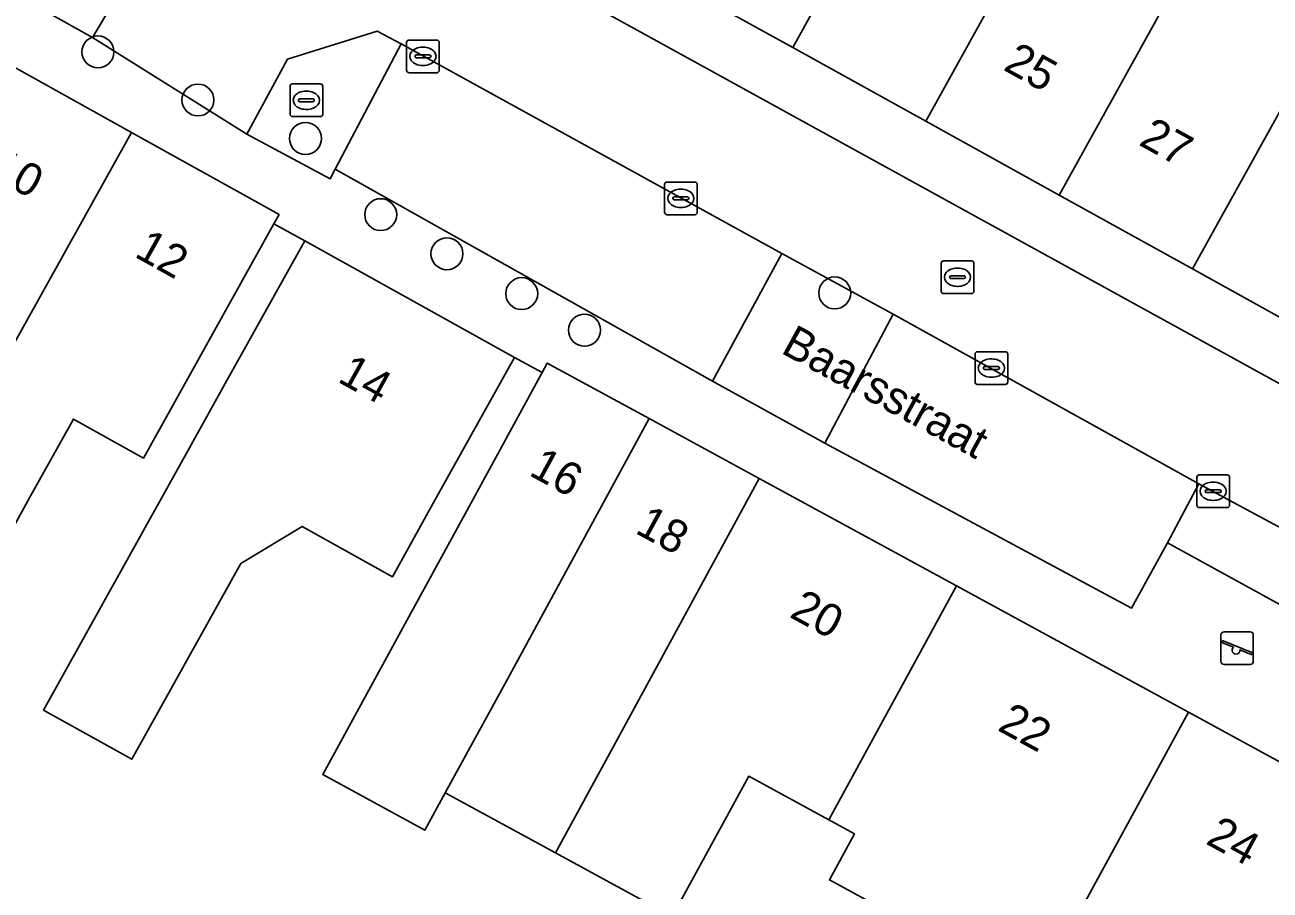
# Model space of a CAD drawing. Extents: x 160102 to 160934, y 382045 to 382923.
# Drawn here: x 160331.35 to 160369.43, y 382187.9 to 382214.38 of the extents above; entities that cross this region are included whole.
import ezdxf

# ---------------------------------------------------------------- set-up
doc = ezdxf.new("R2010")
doc.units = 0
for name, color, linetype in [('IMGEO_Boom', 7, 'Continuous'), ('IMGEO_Brandkraan', 7, 'Continuous'), ('IMGEO_Erf', 7, 'Continuous'), ('IMGEO_Groenvoorziening', 7, 'Continuous'), ('IMGEO_Kolk', 7, 'Continuous'), ('IMGEO_Openbare_ruimte_label', 7, 'Continuous'), ('IMGEO_Pand', 7, 'Continuous'), ('IMGEO_Pand_nummerreeks', 7, 'Continuous'), ('IMGEO_Parkeervlak_open', 7, 'Continuous'), ('IMGEO_Rioolput', 7, 'Continuous'), ('IMGEO_Speelvoorziening', 7, 'Continuous'), ('IMGEO_Verkeerseiland_open', 7, 'Continuous'), ('IMGEO_Voetpad_open', 7, 'Continuous'), ('IMGEO_Woonerf_open', 7, 'Continuous')]:
    doc.layers.add(name, color=color, linetype=linetype)

msp = doc.modelspace()

# ---------------------------------------------------------------- linework, layer by layer
at = {"layer": 'IMGEO_Boom'}
for centre in [(160333.58, 382213.551), (160336.638, 382212.08), (160339.927, 382210.904), (160342.228, 382208.572), (160344.255, 382207.376), (160346.541, 382206.155), (160356.116, 382206.176), (160348.464, 382205.037)]:
    msp.add_circle(centre, 0.489, dxfattribs=at)
at = {"layer": 'IMGEO_Brandkraan'}
for p, q in [((160339.454, 382211.646), (160339.454, 382212.498)), ((160339.529, 382212.572), (160340.381, 382212.572)), ((160339.942, 382212.352), (160339.967, 382212.352)), ((160340.455, 382212.498), (160340.455, 382211.646)), ((160339.713, 382212.066), (160339.713, 382212.078)), ((160340.151, 382212.029), (160339.753, 382212.029)), ((160339.756, 382212.115), (160340.154, 382212.115)), ((160340.197, 382212.078), (160340.197, 382212.066)), ((160340.381, 382211.572), (160339.529, 382211.572)), ((160339.965, 382211.792), (160339.94, 382211.792))]:
    msp.add_line(p, q, dxfattribs=at)
for points in [[(160339.454, 382211.646), (160339.454, 382212.498)], [(160339.529, 382212.572), (160340.381, 382212.572)], [(160340.455, 382212.498), (160340.455, 382211.646)], [(160340.381, 382211.572), (160339.529, 382211.572)]]:
    msp.add_lwpolyline(points, dxfattribs=at)
for centre, radius, start, end in [((160339.531, 382212.496), 0.0765, 91.552, 178.448), ((160339.531, 382212.496), 0.0765, 91.552, 178.448), ((160340.379, 382212.496), 0.0765, 1.552, 88.448), ((160340.379, 382212.496), 0.0765, 1.552, 88.448), ((160339.753, 382212.075), 0.0403, 85.8775, 175.7526), ((160339.75, 382212.065), 0.0366, 178.938, 274.7102), ((160340.154, 382212.072), 0.043, 264.8664, 352.4533), ((160340.158, 382212.077), 0.0386, 1.7309, 96.639), ((160339.531, 382211.648), 0.0765, 181.552, 268.448), ((160339.531, 382211.648), 0.0765, 181.552, 268.448), ((160340.379, 382211.648), 0.0765, 271.552, 358.448), ((160340.379, 382211.648), 0.0765, 271.552, 358.448)]:
    msp.add_arc(centre, radius, start, end, dxfattribs=at)
for centre, major_axis, ratio, start_param, end_param in [((160339.941, 382212.072), (-0.387, 0.002), 0.722429, 4.712389, 7.853982), ((160339.966, 382212.072), (-0.39, 0.002), 0.717154, 1.570796, 4.712389)]:
    msp.add_ellipse(centre, major_axis=major_axis, ratio=ratio, start_param=start_param, end_param=end_param, dxfattribs=at)
at = {"layer": 'IMGEO_Erf'}
msp.add_lwpolyline([(160360.772, 382185.588), (160355.952, 382188.213), (160356.721, 382189.624), (160355.937, 382190.051), (160353.484, 382191.388), (160351.144, 382187.095), (160347.573, 382189.041), (160344.203, 382190.877), (160343.583, 382189.739), (160340.462, 382191.439), (160342.97, 382196.042), (160344.93, 382199.64), (160347.164, 382203.74), (160346.32, 382204.199), (160343.888, 382199.831), (160342.586, 382197.494), (160339.822, 382199.033), (160337.95, 382197.902), (160334.611, 382191.909), (160331.911, 382193.413), (160336.173, 382201.065), (160337.475, 382203.402), (160339.908, 382207.77), (160338.963, 382208.291), (160336.687, 382204.205), (160334.972, 382201.125), (160332.831, 382202.317), (160331.498, 382199.923), (160330.295, 382197.745)], dxfattribs=at)
at = {"layer": 'IMGEO_Groenvoorziening'}
for points in [[(160342.857, 382213.798), (160342.12, 382214.184), (160339.373, 382213.33), (160338.13, 382211.039), (160340.683, 382209.668), (160340.84, 382209.967)], [(160371.499, 382195.671), (160371.728, 382196.05), (160370.985, 382198.327), (160367.256, 382200.334), (160366.293, 382198.53)]]:
    msp.add_lwpolyline(points, close=True, dxfattribs=at)
at = {"layer": 'IMGEO_Kolk'}
for p, q in [((160343.019, 382212.989), (160343.019, 382213.841)), ((160343.094, 382213.915), (160343.946, 382213.915)), ((160344.02, 382213.841), (160344.02, 382212.989)), ((160343.321, 382213.458), (160343.719, 382213.458)), ((160343.507, 382213.695), (160343.532, 382213.695)), ((160343.278, 382213.409), (160343.278, 382213.421)), ((160343.716, 382213.372), (160343.318, 382213.372)), ((160343.53, 382213.135), (160343.505, 382213.135)), ((160343.762, 382213.421), (160343.762, 382213.409)), ((160343.946, 382212.915), (160343.094, 382212.915)), ((160350.909, 382208.645), (160350.909, 382209.497)), ((160350.984, 382209.571), (160351.836, 382209.571)), ((160351.397, 382209.351), (160351.422, 382209.351)), ((160351.91, 382209.497), (160351.91, 382208.645)), ((160351.168, 382209.065), (160351.168, 382209.077)), ((160351.606, 382209.028), (160351.208, 382209.028)), ((160351.211, 382209.114), (160351.609, 382209.114)), ((160351.652, 382209.077), (160351.652, 382209.065)), ((160351.836, 382208.571), (160350.984, 382208.571)), ((160351.42, 382208.791), (160351.395, 382208.791)), ((160360.409, 382203.452), (160360.409, 382204.304)), ((160360.484, 382204.378), (160361.336, 382204.378)), ((160361.41, 382204.304), (160361.41, 382203.452)), ((160360.711, 382203.921), (160361.109, 382203.921)), ((160360.897, 382204.158), (160360.922, 382204.158)), ((160360.668, 382203.872), (160360.668, 382203.884)), ((160361.106, 382203.835), (160360.708, 382203.835)), ((160360.92, 382203.598), (160360.895, 382203.598)), ((160361.152, 382203.884), (160361.152, 382203.872)), ((160361.336, 382203.378), (160360.484, 382203.378)), ((160367.193, 382199.682), (160367.193, 382200.534)), ((160367.268, 382200.608), (160368.12, 382200.608)), ((160368.194, 382200.534), (160368.194, 382199.682)), ((160367.452, 382200.102), (160367.452, 382200.114)), ((160367.495, 382200.151), (160367.893, 382200.151)), ((160367.681, 382200.388), (160367.706, 382200.388)), ((160367.936, 382200.114), (160367.936, 382200.102)), ((160367.89, 382200.065), (160367.492, 382200.065)), ((160367.704, 382199.828), (160367.679, 382199.828)), ((160368.12, 382199.608), (160367.268, 382199.608))]:
    msp.add_line(p, q, dxfattribs=at)
for points in [[(160343.019, 382212.989), (160343.019, 382213.841)], [(160343.094, 382213.915), (160343.946, 382213.915)], [(160344.02, 382213.841), (160344.02, 382212.989)], [(160343.946, 382212.915), (160343.094, 382212.915)], [(160350.909, 382208.645), (160350.909, 382209.497)], [(160350.984, 382209.571), (160351.836, 382209.571)], [(160351.91, 382209.497), (160351.91, 382208.645)], [(160351.836, 382208.571), (160350.984, 382208.571)], [(160360.409, 382203.452), (160360.409, 382204.304)], [(160360.484, 382204.378), (160361.336, 382204.378)], [(160361.41, 382204.304), (160361.41, 382203.452)], [(160361.336, 382203.378), (160360.484, 382203.378)], [(160367.193, 382199.682), (160367.193, 382200.534)], [(160367.268, 382200.608), (160368.12, 382200.608)], [(160368.194, 382200.534), (160368.194, 382199.682)], [(160368.12, 382199.608), (160367.268, 382199.608)]]:
    msp.add_lwpolyline(points, dxfattribs=at)
for centre, radius, start, end in [((160343.096, 382213.839), 0.0765, 91.552, 178.448), ((160343.096, 382213.839), 0.0765, 91.552, 178.448), ((160343.944, 382213.839), 0.0765, 1.552, 88.448), ((160343.944, 382213.839), 0.0765, 1.552, 88.448), ((160343.318, 382213.418), 0.0403, 85.8775, 175.7526), ((160343.723, 382213.42), 0.0386, 1.7309, 96.639), ((160343.315, 382213.408), 0.0366, 178.938, 274.7102), ((160343.719, 382213.415), 0.043, 264.8664, 352.4533), ((160343.096, 382212.991), 0.0765, 181.552, 268.448), ((160343.096, 382212.991), 0.0765, 181.552, 268.448), ((160343.944, 382212.991), 0.0765, 271.552, 358.448), ((160343.944, 382212.991), 0.0765, 271.552, 358.448), ((160350.986, 382209.495), 0.0765, 91.552, 178.448), ((160350.986, 382209.495), 0.0765, 91.552, 178.448), ((160351.834, 382209.495), 0.0765, 1.552, 88.448), ((160351.834, 382209.495), 0.0765, 1.552, 88.448), ((160351.208, 382209.074), 0.0403, 85.8775, 175.7526), ((160351.205, 382209.064), 0.0366, 178.938, 274.7102), ((160351.609, 382209.071), 0.043, 264.8664, 352.4533), ((160351.613, 382209.076), 0.0386, 1.7309, 96.639), ((160350.986, 382208.647), 0.0765, 181.552, 268.448), ((160350.986, 382208.647), 0.0765, 181.552, 268.448), ((160351.834, 382208.647), 0.0765, 271.552, 358.448), ((160351.834, 382208.647), 0.0765, 271.552, 358.448), ((160360.486, 382204.302), 0.0765, 91.552, 178.448), ((160360.486, 382204.302), 0.0765, 91.552, 178.448), ((160361.334, 382204.302), 0.0765, 1.552, 88.448), ((160361.334, 382204.302), 0.0765, 1.552, 88.448), ((160360.708, 382203.881), 0.0403, 85.8775, 175.7526), ((160361.113, 382203.883), 0.0386, 1.7309, 96.639), ((160360.705, 382203.871), 0.0366, 178.938, 274.7102), ((160361.109, 382203.878), 0.043, 264.8664, 352.4533), ((160360.486, 382203.454), 0.0765, 181.552, 268.448), ((160360.486, 382203.454), 0.0765, 181.552, 268.448), ((160361.334, 382203.454), 0.0765, 271.552, 358.448), ((160361.334, 382203.454), 0.0765, 271.552, 358.448), ((160367.27, 382200.532), 0.0765, 91.552, 178.448), ((160367.27, 382200.532), 0.0765, 91.552, 178.448), ((160368.118, 382200.532), 0.0765, 1.552, 88.448), ((160368.118, 382200.532), 0.0765, 1.552, 88.448), ((160367.492, 382200.111), 0.0403, 85.8775, 175.7526), ((160367.897, 382200.113), 0.0386, 1.7309, 96.639), ((160367.489, 382200.101), 0.0366, 178.938, 274.7102), ((160367.893, 382200.108), 0.043, 264.8664, 352.4533), ((160367.27, 382199.684), 0.0765, 181.552, 268.448), ((160367.27, 382199.684), 0.0765, 181.552, 268.448), ((160368.118, 382199.684), 0.0765, 271.552, 358.448), ((160368.118, 382199.684), 0.0765, 271.552, 358.448)]:
    msp.add_arc(centre, radius, start, end, dxfattribs=at)
for centre, major_axis, ratio, start_param, end_param in [((160343.506, 382213.415), (-0.387, 0.002), 0.722429, 4.712389, 7.853982), ((160343.531, 382213.415), (-0.39, 0.002), 0.717154, 1.570796, 4.712389), ((160351.396, 382209.071), (-0.387, 0.002), 0.722429, 4.712389, 7.853982), ((160351.421, 382209.071), (-0.39, 0.002), 0.717154, 1.570796, 4.712389), ((160360.896, 382203.878), (-0.387, 0.002), 0.722429, 4.712389, 7.853982), ((160360.921, 382203.878), (-0.39, 0.002), 0.717154, 1.570796, 4.712389), ((160367.68, 382200.108), (-0.387, 0.002), 0.722429, 4.712389, 7.853982), ((160367.705, 382200.108), (-0.39, 0.002), 0.717154, 1.570796, 4.712389)]:
    msp.add_ellipse(centre, major_axis=major_axis, ratio=ratio, start_param=start_param, end_param=end_param, dxfattribs=at)
at = {"layer": 'IMGEO_Pand'}
for points in [[(160356.399, 382221.875), (160359.053, 382226.666), (160359.886, 382228.17), (160359.468, 382229.511), (160358.55, 382230.019), (160357.247, 382227.667), (160350.753, 382215.945), (160354.83, 382213.686), (160358.669, 382220.617)], [(160365.433, 382223.212), (160363.171, 382224.465), (160360.483, 382219.612), (160358.669, 382220.617), (160354.83, 382213.686), (160358.906, 382211.429)], [(160365.433, 382223.212), (160358.906, 382211.429), (160362.982, 382209.171), (160366.828, 382216.114), (160364.642, 382217.325), (160367.324, 382222.165)], [(160373.581, 382218.687), (160371.305, 382219.948), (160368.628, 382215.117), (160366.828, 382216.114), (160362.982, 382209.171), (160367.059, 382206.912)], [(160374.797, 382211.703), (160372.952, 382212.724), (160375.628, 382217.553), (160373.581, 382218.687), (160367.059, 382206.912), (160371.135, 382204.654), (160374.982, 382211.6)], [(160334.603, 382211.089), (160330.429, 382213.414), (160326.252, 382205.911), (160326.444, 382205.804), (160328.382, 382204.725), (160327.078, 382202.385), (160325.886, 382200.213), (160327.911, 382199.072), (160329.122, 382201.247)], [(160338.963, 382208.291), (160339.12, 382208.573), (160334.603, 382211.089), (160329.122, 382201.247), (160327.911, 382199.072), (160330.295, 382197.745), (160331.498, 382199.923), (160332.831, 382202.317), (160334.972, 382201.125), (160336.687, 382204.205)], [(160339.908, 382207.77), (160337.475, 382203.402), (160336.173, 382201.065), (160331.911, 382193.413), (160334.611, 382191.909), (160337.95, 382197.902), (160339.822, 382199.033), (160342.586, 382197.494), (160343.888, 382199.831), (160346.32, 382204.199)], [(160350.443, 382202.33), (160347.322, 382204.03), (160347.164, 382203.74), (160344.93, 382199.64), (160342.97, 382196.042), (160340.462, 382191.439), (160343.583, 382189.739), (160344.203, 382190.877), (160346.044, 382194.247)], [(160347.573, 382189.041), (160349.355, 382192.314), (160353.808, 382200.496), (160350.443, 382202.33), (160346.044, 382194.247), (160344.203, 382190.877)], [(160347.573, 382189.041), (160351.144, 382187.095), (160353.484, 382191.388), (160355.937, 382190.051), (160359.838, 382197.211), (160353.808, 382200.496), (160349.355, 382192.314)], [(160366.933, 382193.346), (160359.838, 382197.211), (160355.937, 382190.051), (160356.721, 382189.624), (160355.952, 382188.213), (160360.772, 382185.588), (160361.317, 382186.59), (160362.809, 382185.778), (160363.355, 382186.78)], [(160369.779, 382183.28), (160373.356, 382189.847), (160366.933, 382193.346), (160363.355, 382186.78)]]:
    msp.add_lwpolyline(points, close=True, dxfattribs=at)
at = {"layer": 'IMGEO_Parkeervlak_open'}
for points in [[(160342.857, 382213.798), (160340.84, 382209.967), (160352.375, 382203.475), (160354.501, 382207.384)], [(160357.907, 382205.526), (160355.809, 382201.58), (160365.195, 382196.531), (160366.293, 382198.53), (160367.256, 382200.334)]]:
    msp.add_lwpolyline(points, close=True, dxfattribs=at)
at = {"layer": 'IMGEO_Rioolput'}
for p, q in [((160359.372, 382206.232), (160359.372, 382207.084)), ((160359.447, 382207.158), (160360.299, 382207.158)), ((160360.373, 382207.084), (160360.373, 382206.232)), ((160359.631, 382206.652), (160359.631, 382206.664)), ((160360.069, 382206.615), (160359.671, 382206.615)), ((160359.674, 382206.701), (160360.072, 382206.701)), ((160359.86, 382206.938), (160359.885, 382206.938)), ((160360.115, 382206.664), (160360.115, 382206.652)), ((160359.883, 382206.378), (160359.858, 382206.378)), ((160360.299, 382206.158), (160359.447, 382206.158))]:
    msp.add_line(p, q, dxfattribs=at)
for points in [[(160359.372, 382206.232), (160359.372, 382207.084)], [(160359.447, 382207.158), (160360.299, 382207.158)], [(160360.373, 382207.084), (160360.373, 382206.232)], [(160360.299, 382206.158), (160359.447, 382206.158)]]:
    msp.add_lwpolyline(points, dxfattribs=at)
for centre, radius, start, end in [((160359.449, 382207.082), 0.0765, 91.552, 178.448), ((160359.449, 382207.082), 0.0765, 91.552, 178.448), ((160360.297, 382207.082), 0.0765, 1.552, 88.448), ((160360.297, 382207.082), 0.0765, 1.552, 88.448), ((160359.671, 382206.661), 0.0403, 85.8775, 175.7526), ((160359.668, 382206.651), 0.0366, 178.938, 274.7102), ((160360.072, 382206.658), 0.043, 264.8664, 352.4533), ((160360.076, 382206.663), 0.0386, 1.7309, 96.639), ((160359.449, 382206.234), 0.0765, 181.552, 268.448), ((160359.449, 382206.234), 0.0765, 181.552, 268.448), ((160360.297, 382206.234), 0.0765, 271.552, 358.448), ((160360.297, 382206.234), 0.0765, 271.552, 358.448)]:
    msp.add_arc(centre, radius, start, end, dxfattribs=at)
for centre, major_axis, ratio, start_param, end_param in [((160359.859, 382206.658), (-0.387, 0.002), 0.722429, 4.712389, 7.853982), ((160359.884, 382206.658), (-0.39, 0.002), 0.717154, 1.570796, 4.712389)]:
    msp.add_ellipse(centre, major_axis=major_axis, ratio=ratio, start_param=start_param, end_param=end_param, dxfattribs=at)
at = {"layer": 'IMGEO_Speelvoorziening'}
for p, q in [((160367.931, 382194.905), (160367.931, 382195.705)), ((160367.931, 382195.705), (160367.931, 382194.905)), ((160368.031, 382195.805), (160368.821, 382195.805)), ((160368.821, 382195.805), (160368.031, 382195.805)), ((160368.921, 382195.705), (160368.921, 382194.905)), ((160368.921, 382194.905), (160368.921, 382195.705)), ((160368.314, 382195.333), (160367.975, 382195.47)), ((160368, 382195.53), (160368.876, 382195.177)), ((160368.852, 382195.117), (160368.512, 382195.254)), ((160368.821, 382194.805), (160368.031, 382194.805)), ((160368.031, 382194.805), (160368.821, 382194.805))]:
    msp.add_line(p, q, dxfattribs=at)
for centre, radius, start, end in [((160368.031, 382195.705), 0.1, 90, 180), ((160368.031, 382195.705), 0.1, 90, 180), ((160368.821, 382195.705), 0.1, 0, 90), ((160368.821, 382195.705), 0.1, 360, 90), ((160367.988, 382195.5), 0.0327, 68.078, 248.078), ((160368.393, 382195.243), 0.12, 130.9928, 5.1632), ((160368.864, 382195.147), 0.0327, 248.078, 68.078), ((160368.031, 382194.905), 0.1, 180, 270), ((160368.031, 382194.905), 0.1, 180, 270), ((160368.821, 382194.905), 0.1, 270, 0), ((160368.821, 382194.905), 0.1, 270, 0)]:
    msp.add_arc(centre, radius, start, end, dxfattribs=at)
at = {"layer": 'IMGEO_Verkeerseiland_open'}
msp.add_lwpolyline([(160355.809, 382201.58), (160357.907, 382205.526), (160354.501, 382207.384), (160352.375, 382203.475)], close=True, dxfattribs=at)
at = {"layer": 'IMGEO_Voetpad_open'}
for points in [[(160315.073, 382233.968), (160336.5, 382221.696), (160339.939, 382219.805), (160376.326, 382199.761), (160378.158, 382198.749), (160396.659, 382188.529), (160397.584, 382190.075), (160392.804, 382192.661), (160387.976, 382195.273), (160383.191, 382197.861), (160380.289, 382199.583), (160375.251, 382202.374), (160371.135, 382204.654), (160367.059, 382206.912), (160362.982, 382209.171), (160358.906, 382211.429), (160354.83, 382213.686), (160350.753, 382215.945), (160346.239, 382218.446), (160341.726, 382220.946), (160337.65, 382223.204), (160333.574, 382225.462), (160329.498, 382227.72)], [(160381.352, 382187.841), (160382.342, 382189.627), (160379.655, 382191.116), (160375.281, 382193.541), (160371.499, 382195.671), (160366.293, 382198.53), (160365.195, 382196.531), (160355.809, 382201.58), (160352.375, 382203.475), (160340.84, 382209.967), (160340.683, 382209.668), (160338.13, 382211.039), (160333.417, 382213.994), (160329.18, 382216.354)], [(160330.429, 382213.414), (160334.603, 382211.089), (160339.12, 382208.573), (160338.963, 382208.291), (160339.908, 382207.77), (160346.32, 382204.199), (160347.164, 382203.74), (160347.322, 382204.03), (160350.443, 382202.33), (160353.808, 382200.496), (160359.838, 382197.211), (160366.933, 382193.346), (160373.356, 382189.847), (160379.425, 382186.54)]]:
    msp.add_lwpolyline(points, dxfattribs=at)
at = {"layer": 'IMGEO_Woonerf_open'}
for points in [[(160334.333, 382217.831), (160334.036, 382217.982), (160331.022, 382219.661), (160329.18, 382216.354), (160333.417, 382213.994), (160335.341, 382217.23)], [(160339.939, 382219.805), (160339.063, 382218.187), (160335.341, 382217.23), (160333.417, 382213.994), (160338.13, 382211.039), (160339.373, 382213.33), (160342.12, 382214.184), (160342.857, 382213.798), (160354.501, 382207.384), (160357.907, 382205.526), (160367.256, 382200.334), (160370.985, 382198.327), (160371.728, 382196.05), (160371.499, 382195.671), (160375.281, 382193.541), (160377.171, 382196.897), (160376.776, 382197.141), (160376.157, 382199.476), (160376.326, 382199.761)]]:
    msp.add_lwpolyline(points, close=True, dxfattribs=at)

# ---------------------------------------------------------------- texts
at = {"layer": 'IMGEO_Openbare_ruimte_label'}
msp.add_text('Baarsstraat', height=1, rotation=331.385, dxfattribs=at).set_placement((160354.436, 382204.357))
at = {"layer": 'IMGEO_Pand_nummerreeks'}
for s, rotation, p in [('25', 331.0155, (160361.238, 382213.018)), ('27', 331.0155, (160365.384, 382210.722)), ('10', 330.8823, (160330.231, 382209.769)), ('12', 330.8823, (160334.661, 382207.302)), ('14', 330.8855, (160340.876, 382203.477)), ('16', 331.4155, (160346.728, 382200.618)), ('18', 331.4155, (160349.974, 382198.849)), ('20', 331.4189, (160354.699, 382196.275)), ('22', 331.4209, (160361.062, 382192.81)), ('24', 331.4189, (160367.431, 382189.338))]:
    msp.add_text(s, height=1, rotation=rotation, dxfattribs=at).set_placement(p)

doc.saveas('drawing.dxf')
